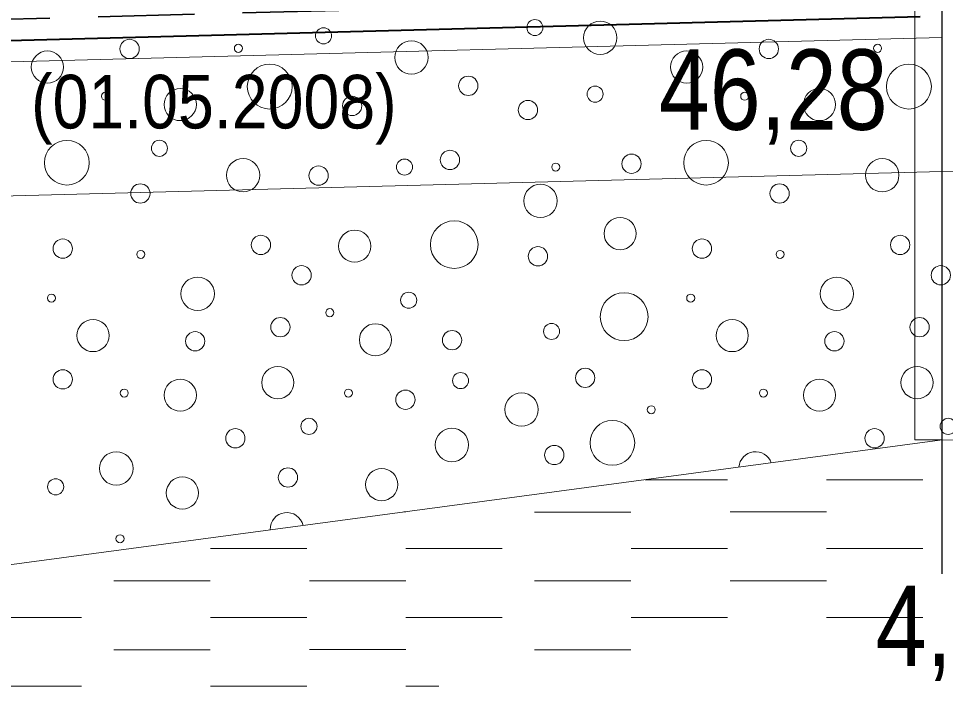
# Model space of a CAD drawing. Extents: x 640121 to 640955, y 6441885 to 6442246.
# Drawn here: x 640886.22 to 640920.83, y 6442117.26 to 6442142.78 of the extents above; entities that cross this region are included whole.
import ezdxf
from ezdxf.enums import TextEntityAlignment as Align

# ---------------------------------------------------------------- set-up
doc = ezdxf.new("R2010")
doc.units = 0
doc.header["$LTSCALE"] = 1.2
doc.linetypes.add('MEDIUM_DASHED', pattern=[4.5, 3, -1.5])
for name, color, linetype, lineweight in [('31', 7, 'Continuous', 13), ('32', 7, 'Continuous', 13), ('33', 7, 'Continuous', 13), ('34', 7, 'Continuous', 25), ('35', 7, 'Continuous', 35), ('41', 7, 'Continuous', 13), ('46', 7, 'Continuous', 13)]:
    doc.layers.add(name, color=color, linetype=linetype, lineweight=lineweight)

msp = doc.modelspace()

# ---------------------------------------------------------------- linework, layer by layer
at = {"layer": '31'}
msp.add_lwpolyline([(640635.03, 6442075.9), (640649.8, 6442077.26), (640785.83, 6442102.65), (640874.62, 6442120.89), (640920.62, 6442127.04), (640933.07, 6442127.28)], dxfattribs=at)
at = {"layer": '32', "lineweight": 25}
msp.add_line((640920.69, 6442167.06), (640920.69, 6442122.06), dxfattribs=at)
at = {"layer": '33'}
msp.add_lwpolyline([(640919.69, 6442151.91), (640919.69, 6442127.06), (640920.62, 6442127.06), (640920.69, 6442127.06), (640920.69, 6442152.04)], close=True, dxfattribs=at)
at = {"layer": '34', "lineweight": 13}
msp.add_lwpolyline([(640635.03, 6442126.63), (640785.8, 6442131.67), (640874.6, 6442135.86), (640933.07, 6442137.4)], dxfattribs=at)
at = {"layer": '35', "linetype": 'MEDIUM_DASHED'}
msp.add_line((640872.99, 6442142.42), (640919.09, 6442143.64), dxfattribs=at)
at = {"layer": '35', "lineweight": 40}
msp.add_line((640873.79, 6442141.65), (640919.89, 6442142.86), dxfattribs=at)
at = {"layer": '35', "lineweight": 13}
msp.add_line((640874.59, 6442140.87), (640920.69, 6442142.08), dxfattribs=at)
at = {"layer": '41'}
for centre, radius in [((640905.499, 6442142.444), 0.3), ((640907.938, 6442142.064), 0.624), ((640897.605, 6442142.135), 0.3), ((640890.363, 6442141.647), 0.36), ((640894.425, 6442141.67), 0.15), ((640900.887, 6442141.328), 0.624), ((640914.232, 6442141.647), 0.36), ((640918.294, 6442141.67), 0.15), ((640887.294, 6442140.971), 0.6), ((640911.163, 6442140.971), 0.6), ((640895.595, 6442140.242), 0.838), ((640919.464, 6442140.242), 0.838), ((640903.011, 6442140.271), 0.36), ((640889.463, 6442139.882), 0.15), ((640892.256, 6442139.57), 0.6), ((640907.746, 6442139.96), 0.3), ((640913.332, 6442139.882), 0.15), ((640916.125, 6442139.57), 0.6), ((640898.674, 6442139.52), 0.36), ((640905.238, 6442139.368), 0.36), ((640888.021, 6442137.401), 0.834), ((640891.479, 6442137.938), 0.3), ((640911.89, 6442137.401), 0.834), ((640915.348, 6442137.938), 0.3), ((640902.327, 6442137.505), 0.36), ((640909.107, 6442137.361), 0.36), ((640894.601, 6442136.933), 0.624), ((640897.42, 6442136.918), 0.36), ((640900.629, 6442137.239), 0.3), ((640906.276, 6442137.239), 0.15), ((640918.47, 6442136.933), 0.624), ((640890.766, 6442136.253), 0.36), ((640905.707, 6442135.975), 0.624), ((640914.635, 6442136.253), 0.36), ((640902.487, 6442134.343), 0.889), ((640908.679, 6442134.755), 0.6), ((640898.769, 6442134.287), 0.6), ((640887.868, 6442134.194), 0.36), ((640895.267, 6442134.332), 0.36), ((640911.737, 6442134.194), 0.36), ((640919.136, 6442134.332), 0.36), ((640905.613, 6442133.908), 0.36), ((640890.783, 6442133.978), 0.15), ((640914.652, 6442133.978), 0.15), ((640896.786, 6442133.2), 0.36), ((640920.655, 6442133.2), 0.36), ((640892.905, 6442132.507), 0.624), ((640916.774, 6442132.507), 0.624), ((640887.447, 6442132.346), 0.15), ((640900.785, 6442132.268), 0.3), ((640908.83, 6442131.654), 0.893), ((640911.316, 6442132.346), 0.15), ((640897.839, 6442131.803), 0.15), ((640888.998, 6442130.948), 0.6), ((640895.994, 6442131.262), 0.36), ((640899.543, 6442130.792), 0.6), ((640906.12, 6442131.104), 0.3), ((640912.867, 6442130.948), 0.6), ((640919.863, 6442131.262), 0.36), ((640892.813, 6442130.737), 0.36), ((640902.405, 6442130.779), 0.36), ((640916.682, 6442130.737), 0.36), ((640887.868, 6442129.315), 0.36), ((640895.898, 6442129.192), 0.6), ((640907.375, 6442129.372), 0.36), ((640911.737, 6442129.315), 0.36), ((640919.767, 6442129.192), 0.6), ((640892.256, 6442128.724), 0.6), ((640902.723, 6442129.267), 0.3), ((640916.125, 6442128.724), 0.6), ((640890.162, 6442128.802), 0.15), ((640898.535, 6442128.802), 0.15), ((640914.031, 6442128.802), 0.15), ((640900.664, 6442128.555), 0.36), ((640905, 6442128.186), 0.624), ((640909.843, 6442128.181), 0.15), ((640897.062, 6442127.56), 0.3), ((640908.391, 6442126.944), 0.835), ((640920.931, 6442127.56), 0.3), ((640894.313, 6442127.114), 0.36), ((640902.398, 6442126.866), 0.624), ((640918.182, 6442127.114), 0.36), ((640889.868, 6442125.988), 0.624), ((640906.223, 6442126.491), 0.36), ((640896.277, 6442125.653), 0.36), ((640899.777, 6442125.385), 0.6), ((640887.603, 6442125.304), 0.3), ((640892.334, 6442125.073), 0.6), ((640890.006, 6442123.366), 0.15)]:
    msp.add_circle(centre, radius, dxfattribs=at)
for centre, start, end in [((640913.737, 6442125.988), 20.0535, 175.1814), ((640896.236, 6442123.72), 13.378, 181.8569)]:
    msp.add_arc(centre, 0.624, start, end, dxfattribs=at)
at = {"layer": '46'}
for p, q in [((640912.69, 6442125.57), (640909.62, 6442125.57)), ((640919.99, 6442125.57), (640916.39, 6442125.57)), ((640900.68, 6442124.37), (640900.61, 6442124.37)), ((640909.08, 6442124.36), (640905.48, 6442124.36)), ((640916.39, 6442124.37), (640912.79, 6442124.37)), ((640896.98, 6442123), (640893.38, 6442123)), ((640904.28, 6442123), (640900.68, 6442123)), ((640912.69, 6442123), (640909.09, 6442123)), ((640919.99, 6442123), (640916.39, 6442123)), ((640893.37, 6442121.79), (640889.77, 6442121.79)), ((640900.68, 6442121.8), (640897.08, 6442121.8)), ((640909.08, 6442121.79), (640905.48, 6442121.79)), ((640916.39, 6442121.8), (640912.79, 6442121.8)), ((640888.57, 6442120.43), (640884.97, 6442120.43)), ((640896.98, 6442120.43), (640893.38, 6442120.43)), ((640904.28, 6442120.43), (640900.68, 6442120.43)), ((640912.69, 6442120.43), (640909.09, 6442120.43)), ((640919.99, 6442120.43), (640916.39, 6442120.43)), ((640893.37, 6442119.22), (640889.77, 6442119.22)), ((640900.68, 6442119.23), (640897.08, 6442119.23)), ((640909.08, 6442119.22), (640905.48, 6442119.22)), ((640888.57, 6442117.86), (640884.97, 6442117.86)), ((640896.98, 6442117.86), (640893.38, 6442117.86)), ((640901.91, 6442117.86), (640900.68, 6442117.86))]:
    msp.add_line(p, q, dxfattribs=at)

# ---------------------------------------------------------------- texts
at = {"layer": '32', "width": 0.85}
for s, p in [('46,28', (640914.4, 6442138.63)), ('4,5', (640920.595, 6442118.61))]:
    msp.add_text(s, height=3, dxfattribs=at).set_placement(p, align=Align.CENTER)
at = {"layer": '34', "width": 0.9}
msp.add_text('(01.05.2008)', height=2, dxfattribs=at).set_placement((640893.51, 6442138.68), align=Align.CENTER)

doc.saveas('drawing.dxf')
